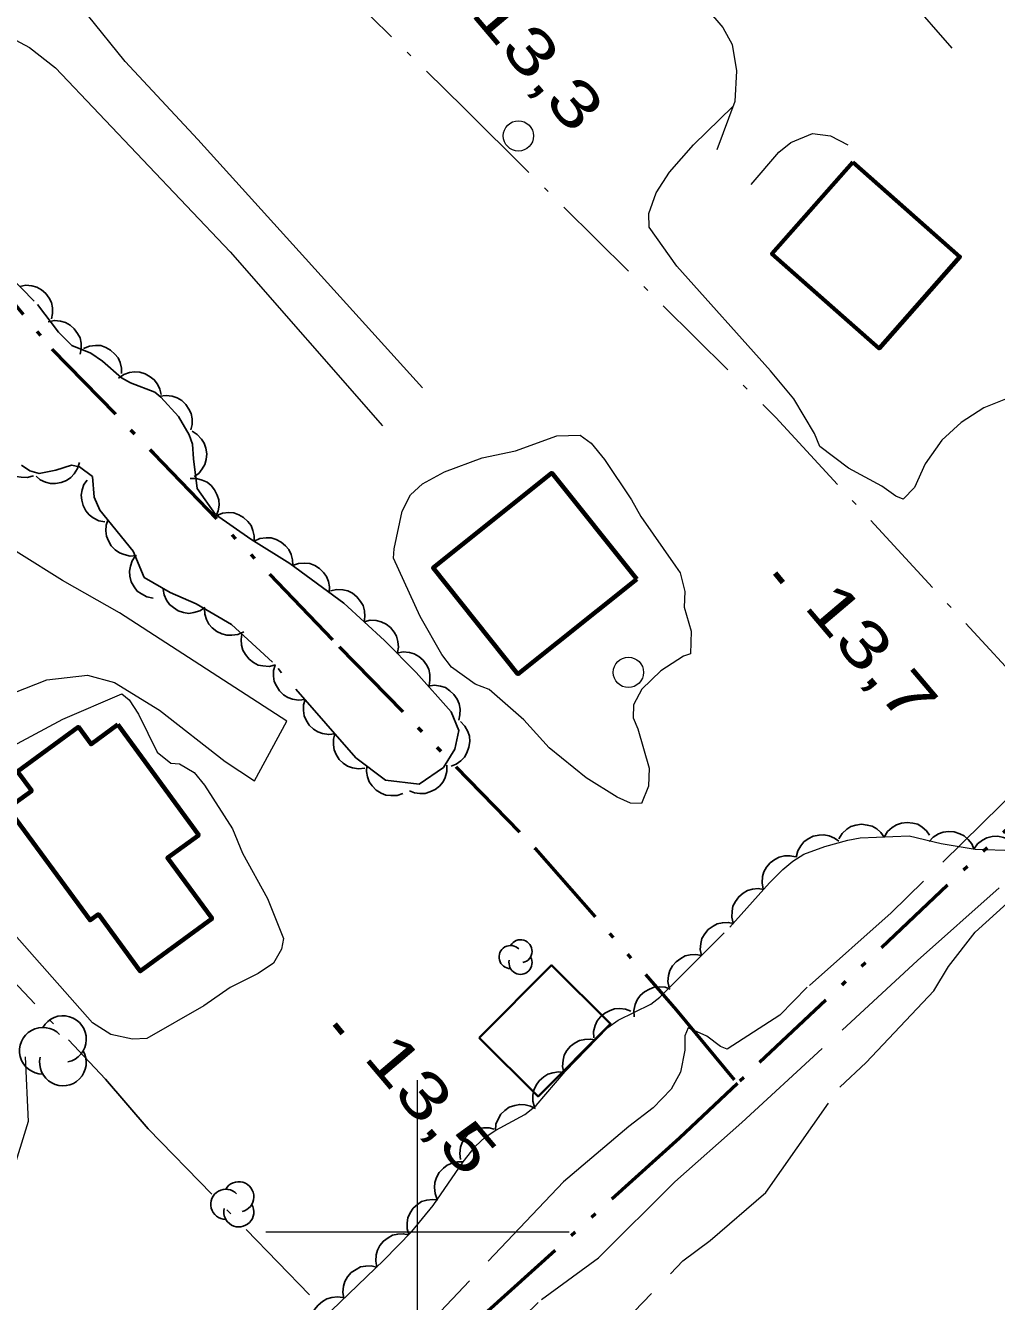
# Model space of a CAD drawing. Extents: x 386081 to 389416, y 5130568 to 5134082.
# Drawn here: x 387174.2 to 387238.2, y 5131995.4 to 5132079.6 of the extents above; entities that cross this region are included whole.
import ezdxf

# ---------------------------------------------------------------- set-up
doc = ezdxf.new("R2010")
doc.units = 0
doc.header["$LTSCALE"] = 1.2
for name, pattern in [('DASH_DOUBLE_DOT', [9.2, 5, -1.2, 0.3, -1.2, 0.3, -1.2]), ('DOT_DASHED', [7.7, 5, -1.2, 0.3, -1.2]), ('LONG_DASHED', [7.5, 6, -1.5])]:
    doc.linetypes.add(name, pattern=pattern)
for name, color, linetype, lineweight in [('19', 7, 'Continuous', 13), ('2', 7, 'Continuous', 13), ('3', 7, 'Continuous', 140), ('31', 7, 'Continuous', 70), ('36', 7, 'Continuous', 13), ('4', 7, 'DASH_DOUBLE_DOT', 53), ('41', 7, 'DOT_DASHED', 25), ('44', 7, 'Continuous', 25), ('61', 7, 'Continuous', 13)]:
    doc.layers.add(name, color=color, linetype=linetype, lineweight=lineweight)

msp = doc.modelspace()

# ---------------------------------------------------------------- linework, layer by layer
at = {"layer": '19'}
for points in [[(387235.25, 5132078.05), (387232.36, 5132081.38), (387229.88, 5132084.04), (387228.02, 5132082.24), (387226.25, 5132081.78), (387224.8, 5132082.21), (387223.27, 5132083.15), (387219.82, 5132086.04), (387214.56, 5132090.74), (387205.62, 5132099.47), (387202.19, 5132103.97), (387201.34, 5132105.59), (387201.05, 5132106.83), (387201.2, 5132108.09)], [(387195.48, 5132102.28), (387197.31, 5132101.55), (387199.4, 5132100.21), (387201.37, 5132098.51), (387212.87, 5132087.29), (387217.84, 5132082.11), (387220.13, 5132079.43), (387220.75, 5132078.3), (387221.02, 5132076.57), (387220.91, 5132074.55), (387219.74, 5132071.36)], [(387200.33, 5132055.65), (387185.51, 5132072.03), (387180.72, 5132077.18), (387178.24, 5132080.25), (387177.34, 5132081.59), (387176.74, 5132082.8), (387176.67, 5132083.63)], [(387171.93, 5132079.41), (387174.41, 5132078.09), (387176.13, 5132076.76), (387187.64, 5132064.63), (387197.68, 5132053.15)], [(387221.99, 5132069.07), (387223.82, 5132071.21), (387224.61, 5132071.84), (387226.04, 5132072.44), (387227.22, 5132072.28), (387228.37, 5132071.69)], [(387172.65, 5132035.26), (387175.55, 5132036.4), (387178.24, 5132036.72), (387180.02, 5132036.24), (387182.98, 5132034.41), (387187.32, 5132031.03), (387189.24, 5132029.75), (387191.38, 5132033.67), (387180.35, 5132040.82), (387176.6, 5132042.96), (387167.93, 5132048.36)], [(387174.13, 5132011.55), (387174.32, 5132007.28), (387173.26, 5132003.79)]]:
    msp.add_lwpolyline(points, dxfattribs=at)
at = {"layer": '2'}
for points in [[(387239.21, 5132055.08), (387237.34, 5132054.34), (387235.84, 5132053.38), (387234.57, 5132052.2), (387233.47, 5132050.65), (387232.76, 5132049.09), (387232.02, 5132048.32), (387231.52, 5132048.51), (387230.6, 5132049.18), (387228.42, 5132050.36), (387226.52, 5132051.79), (387226.16, 5132052.65), (387224.8, 5132054.94), (387223.27, 5132056.79), (387217.1, 5132063.68), (387215.26, 5132066.25), (387215.24, 5132067.15), (387215.73, 5132068.51), (387216.62, 5132069.88), (387218.2, 5132071.68), (387220.79, 5132074.21)], [(387171.81, 5132031.24), (387176.62, 5132033.82), (387180.51, 5132035.48), (387180.98, 5132035.09), (387181.61, 5132034.15), (387182.83, 5132031.63), (387183.74, 5132030.92), (387184.31, 5132030.86), (387185.28, 5132030.3), (387185.95, 5132029.46), (387187.79, 5132026.59), (387188.47, 5132024.98), (387190.11, 5132021.98), (387191.17, 5132019.34), (387191.04, 5132018.65), (387190.5, 5132017.73), (387189.5, 5132017.04), (387187.65, 5132016.11), (387185.91, 5132014.9), (387182.15, 5132012.76), (387181.2, 5132012.71), (387179.78, 5132013.03), (387178.56, 5132013.78), (387172.93, 5132020.19)]]:
    msp.add_lwpolyline(points, dxfattribs=at)
at = {"layer": '2', "linetype": 'LONG_DASHED'}
for points in [[(387264.61, 5132052.7), (387262.48, 5132051.58), (387256.69, 5132046.94), (387254.18, 5132044.13), (387249.06, 5132039), (387244.41, 5132034.13), (387239.76, 5132029.44), (387231.22, 5132021.04), (387225.69, 5132016.13), (387223.88, 5132014.3), (387220.42, 5132012.05), (387219.97, 5132012.22), (387219.08, 5132012.91), (387217.84, 5132013.45), (387217.63, 5132012.93), (387217.63, 5132011.99), (387217.33, 5132010.54), (387216.72, 5132009.42), (387215.53, 5132008.18), (387213.92, 5132006.96), (387209.62, 5132003.3), (387196.04, 5131989.01), (387193.68, 5131986.98), (387181.72, 5131978.95)], [(387195.16, 5131966.17), (387195.01, 5131966.62), (387195.11, 5131967.92), (387195.83, 5131972.22), (387197.11, 5131974.15), (387201.28, 5131979.8), (387206.75, 5131986.68), (387210.42, 5131990.76), (387217.49, 5131998.09), (387219.3, 5131999.44), (387222.96, 5132002.61), (387227.84, 5132009.55), (387229.57, 5132011.18), (387234.04, 5132015.9), (387235, 5132017.51), (387236.75, 5132019.76), (387262.28, 5132042.99)], [(387202.76, 5131990.36), (387208.17, 5131995.54), (387211.92, 5131998.3), (387216.97, 5132003.3), (387221.38, 5132007.21), (387232.96, 5132017.9), (387247.54, 5132030.88)]]:
    msp.add_lwpolyline(points, dxfattribs=at)
at = {"layer": '2'}
msp.add_lwpolyline([(387217, 5132043.9), (387217.31, 5132043.46), (387217.63, 5132042.24), (387217.58, 5132041.19), (387218.03, 5132039.61), (387217.99, 5132038.13), (387217.54, 5132037.96), (387216.04, 5132036.99), (387214.79, 5132035.79), (387214.24, 5132034.75), (387214.22, 5132033.91), (387214.52, 5132033.18), (387215.27, 5132030.58), (387215.23, 5132029.4), (387214.76, 5132028.25), (387214.04, 5132028.28), (387213.16, 5132028.66), (387211.12, 5132029.94), (387208.67, 5132031.92), (387207.01, 5132033.76), (387204.71, 5132035.76), (387203.8, 5132036.11), (387202.24, 5132037.24), (387201.61, 5132038.07), (387200.18, 5132040.59), (387198.41, 5132044.42), (387198.45, 5132045.05), (387198.98, 5132047.53), (387199.54, 5132048.61), (387200.32, 5132049.32), (387201.77, 5132050.13), (387204.25, 5132051.04), (387206.46, 5132051.51), (387209.19, 5132052.49), (387210.72, 5132052.53), (387211.45, 5132052.01), (387212.33, 5132050.94), (387214.1, 5132048.28), (387214.71, 5132047.18)], close=True, dxfattribs=at)
at = {"layer": '3'}
for p, q in [((387223.57, 5132043.44), (387224.08, 5132042.83)), ((387194.54, 5132013.7), (387195.05, 5132013.09))]:
    msp.add_line(p, q, dxfattribs=at)
at = {"layer": '31'}
for points in [[(387228.69, 5132070.54), (387235.76, 5132064.3), (387230.43, 5132058.26), (387223.36, 5132064.5)], [(387214.46, 5132043.05), (387206.62, 5132036.79), (387201.02, 5132043.78), (387208.85, 5132050.05)], [(387180.23, 5132033.45), (387185.58, 5132026.17), (387183.51, 5132024.66), (387186.45, 5132020.66), (387181.72, 5132017.19), (387178.96, 5132020.95), (387178.41, 5132020.55), (387172.99, 5132027.94), (387174.56, 5132029.09), (387173.63, 5132030.36), (387177.64, 5132033.3), (387178.48, 5132032.16)]]:
    msp.add_lwpolyline(points, close=True, dxfattribs=at)
at = {"layer": '31', "lineweight": 35}
msp.add_lwpolyline([(387204.07, 5132012.8), (387208.84, 5132017.59), (387212.72, 5132013.73), (387207.95, 5132008.94)], close=True, dxfattribs=at)
at = {"layer": '36'}
for centre in [(387206.648, 5132072.27), (387213.901, 5132036.897)]:
    msp.add_circle(centre, 1, dxfattribs=at)
at = {"layer": '4'}
for points in [[(387318.59, 5132105.79), (387271.28, 5132059.47), (387242.97, 5132030.44), (387221.09, 5132009.79)], [(387165.87, 5132070.73), (387170.18, 5132065.12), (387175.88, 5132058.2), (387182.6, 5132051.34), (387194.84, 5132038.59), (387207.76, 5132025.29), (387217.04, 5132014.65), (387221.09, 5132009.79), (387217.26, 5132006.18), (387178.99, 5131971.65)]]:
    msp.add_lwpolyline(points, dxfattribs=at)
at = {"layer": '41'}
for points in [[(387187.42, 5132089.5), (387203.08, 5132074.09), (387223.62, 5132053.7), (387241.48, 5132034.32)], [(387144.02, 5132047.08), (387157.99, 5132032.87), (387179.42, 5132010.08)], [(387179.42, 5132010.08), (387182.25, 5132006.79), (387193.01, 5131995.72)]]:
    msp.add_lwpolyline(points, dxfattribs=at)
at = {"layer": '44', "linetype": 'DOT_DASHED'}
msp.add_lwpolyline([(387170.52, 5132065.66), (387174.95, 5132061.15), (387176.32, 5132059.34), (387177.21, 5132058.44), (387178.45, 5132057.94), (387179.24, 5132057.42), (387180.48, 5132056.32), (387181.07, 5132056), (387182.69, 5132055.38), (387183.07, 5132055.04), (387184.23, 5132053.78), (387184.95, 5132052.55), (387185.17, 5132051.95), (387185.22, 5132050.97), (387185.46, 5132049.03), (387186.68, 5132047.3), (387189.01, 5132045.69), (387191.58, 5132044.08), (387195.13, 5132041.47), (387197.82, 5132039), (387199.9, 5132036.9), (387202.22, 5132034.3), (387202.71, 5132033.07), (387202.45, 5132031.84), (387201.71, 5132030.62), (387200.1, 5132029.53), (387197.89, 5132029.79), (387195.93, 5132031.27), (387190.43, 5132037.57), (387187.74, 5132040.05), (387185.41, 5132041.42), (387183.69, 5132042.16), (387181.98, 5132043.16), (387181.25, 5132044.88), (387179.06, 5132047.6), (387178.69, 5132048.46), (387178.58, 5132049.81), (387177.72, 5132050.44), (387177.19, 5132050.57), (387176.15, 5132050.24), (387175.06, 5132050.01), (387174.45, 5132050.19), (387173.88, 5132050.55)], dxfattribs=at)
at = {"layer": '44'}
for points in [[(387173.77, 5132062.35), (387174.18, 5132062.43), (387174.58, 5132062.38), (387174.9, 5132062.3), (387175.21, 5132062.12), (387175.49, 5132061.88), (387175.71, 5132061.57), (387175.86, 5132061.28), (387175.93, 5132060.94), (387175.94, 5132060.56), (387175.87, 5132060.21)], [(387175.65, 5132060.02), (387176.06, 5132060.1), (387176.46, 5132060.05), (387176.78, 5132059.97), (387177.09, 5132059.79), (387177.37, 5132059.55), (387177.59, 5132059.24), (387177.75, 5132058.95), (387177.82, 5132058.61), (387177.83, 5132058.24), (387177.76, 5132057.89)], [(387177.98, 5132058.25), (387178.37, 5132058.41), (387178.77, 5132058.45), (387179.11, 5132058.44), (387179.44, 5132058.32), (387179.76, 5132058.15), (387180.04, 5132057.89), (387180.26, 5132057.64), (387180.4, 5132057.32), (387180.49, 5132056.96), (387180.49, 5132056.6)], [(387180.29, 5132056.3), (387180.64, 5132056.54), (387181.02, 5132056.66), (387181.35, 5132056.72), (387181.7, 5132056.69), (387182.05, 5132056.58), (387182.38, 5132056.39), (387182.64, 5132056.19), (387182.85, 5132055.91), (387183.01, 5132055.58), (387183.09, 5132055.23)], [(387183.02, 5132055.1), (387183.43, 5132055.16), (387183.83, 5132055.1), (387184.15, 5132055.01), (387184.45, 5132054.82), (387184.72, 5132054.57), (387184.93, 5132054.25), (387185.08, 5132053.96), (387185.13, 5132053.61), (387185.13, 5132053.24), (387185.05, 5132052.89)], [(387185.13, 5132052.8), (387185.48, 5132052.59), (387185.76, 5132052.28), (387185.94, 5132052.01), (387186.05, 5132051.68), (387186.1, 5132051.31), (387186.06, 5132050.93), (387185.98, 5132050.61), (387185.8, 5132050.31), (387185.57, 5132050.02), (387185.28, 5132049.81)], [(387174.68, 5132049.85), (387174.27, 5132049.74), (387173.87, 5132049.76), (387173.54, 5132049.82), (387173.23, 5132049.97), (387172.93, 5132050.19), (387172.69, 5132050.49), (387172.51, 5132050.76), (387172.42, 5132051.1), (387172.38, 5132051.47), (387172.42, 5132051.83)], [(387177.71, 5132050.74), (387177.59, 5132050.33), (387177.37, 5132049.99), (387177.15, 5132049.75), (387176.85, 5132049.56), (387176.51, 5132049.42), (387176.13, 5132049.36), (387175.81, 5132049.35), (387175.47, 5132049.45), (387175.13, 5132049.6), (387174.85, 5132049.83)], [(387179.39, 5132046.83), (387178.98, 5132046.9), (387178.62, 5132047.09), (387178.35, 5132047.29), (387178.14, 5132047.56), (387177.96, 5132047.89), (387177.87, 5132048.26), (387177.83, 5132048.58), (387177.89, 5132048.93), (387178.01, 5132049.28), (387178.21, 5132049.58)], [(387185.01, 5132049.68), (387185.42, 5132049.68), (387185.81, 5132049.57), (387186.12, 5132049.44), (387186.39, 5132049.22), (387186.62, 5132048.93), (387186.79, 5132048.59), (387186.9, 5132048.28), (387186.91, 5132047.93), (387186.86, 5132047.56), (387186.73, 5132047.22)], [(387186.76, 5132047.25), (387187.15, 5132047.4), (387187.55, 5132047.43), (387187.88, 5132047.41), (387188.21, 5132047.29), (387188.53, 5132047.11), (387188.81, 5132046.84), (387189.02, 5132046.59), (387189.15, 5132046.26), (387189.23, 5132045.9), (387189.23, 5132045.54)], [(387181.47, 5132044.61), (387181.05, 5132044.57), (387180.66, 5132044.66), (387180.34, 5132044.77), (387180.06, 5132044.98), (387179.81, 5132045.25), (387179.62, 5132045.58), (387179.49, 5132045.88), (387179.46, 5132046.23), (387179.48, 5132046.6), (387179.59, 5132046.94)], [(387189.23, 5132045.55), (387189.61, 5132045.72), (387190.02, 5132045.77), (387190.35, 5132045.77), (387190.68, 5132045.66), (387191.01, 5132045.49), (387191.3, 5132045.24), (387191.52, 5132045), (387191.66, 5132044.68), (387191.76, 5132044.32), (387191.77, 5132043.96)], [(387182.56, 5132041.8), (387182.15, 5132041.88), (387181.79, 5132042.07), (387181.52, 5132042.26), (387181.31, 5132042.54), (387181.13, 5132042.86), (387181.04, 5132043.24), (387181, 5132043.56), (387181.07, 5132043.91), (387181.19, 5132044.26), (387181.39, 5132044.56)], [(387191.76, 5132043.94), (387192.16, 5132044.08), (387192.56, 5132044.1), (387192.89, 5132044.08), (387193.22, 5132043.95), (387193.54, 5132043.75), (387193.8, 5132043.48), (387194, 5132043.22), (387194.13, 5132042.89), (387194.2, 5132042.53), (387194.18, 5132042.17)], [(387185.99, 5132041.17), (387185.64, 5132040.95), (387185.24, 5132040.84), (387184.92, 5132040.79), (387184.57, 5132040.84), (387184.22, 5132040.96), (387183.9, 5132041.17), (387183.64, 5132041.37), (387183.45, 5132041.66), (387183.3, 5132042), (387183.23, 5132042.36)], [(387194.26, 5132042.27), (387194.67, 5132042.36), (387195.08, 5132042.34), (387195.4, 5132042.27), (387195.71, 5132042.11), (387196, 5132041.88), (387196.24, 5132041.58), (387196.41, 5132041.3), (387196.5, 5132040.96), (387196.53, 5132040.59), (387196.47, 5132040.24)], [(387188.54, 5132039.58), (387188.16, 5132039.4), (387187.76, 5132039.34), (387187.43, 5132039.34), (387187.09, 5132039.43), (387186.76, 5132039.59), (387186.46, 5132039.84), (387186.24, 5132040.07), (387186.08, 5132040.39), (387185.97, 5132040.74), (387185.95, 5132041.1)], [(387196.47, 5132040.24), (387196.88, 5132040.33), (387197.28, 5132040.31), (387197.61, 5132040.24), (387197.92, 5132040.08), (387198.21, 5132039.86), (387198.45, 5132039.55), (387198.62, 5132039.28), (387198.71, 5132038.93), (387198.74, 5132038.56), (387198.68, 5132038.21)], [(387190.63, 5132037.39), (387190.22, 5132037.29), (387189.81, 5132037.32), (387189.49, 5132037.38), (387189.18, 5132037.55), (387188.89, 5132037.77), (387188.65, 5132038.08), (387188.48, 5132038.36), (387188.4, 5132038.7), (387188.37, 5132039.07), (387188.42, 5132039.42)], [(387198.64, 5132038.17), (387199.05, 5132038.25), (387199.46, 5132038.2), (387199.78, 5132038.12), (387200.08, 5132037.94), (387200.36, 5132037.7), (387200.58, 5132037.39), (387200.74, 5132037.11), (387200.81, 5132036.76), (387200.82, 5132036.39), (387200.76, 5132036.04)], [(387192.58, 5132035.11), (387192.16, 5132035.06), (387191.76, 5132035.13), (387191.45, 5132035.23), (387191.16, 5132035.42), (387190.89, 5132035.68), (387190.69, 5132036.01), (387190.55, 5132036.3), (387190.5, 5132036.65), (387190.51, 5132037.02), (387190.61, 5132037.37)], [(387200.71, 5132035.99), (387201.12, 5132036.05), (387201.52, 5132035.98), (387201.84, 5132035.89), (387202.13, 5132035.69), (387202.4, 5132035.44), (387202.61, 5132035.12), (387202.75, 5132034.82), (387202.8, 5132034.47), (387202.79, 5132034.1), (387202.71, 5132033.75)], [(387194.55, 5132032.85), (387194.14, 5132032.8), (387193.74, 5132032.87), (387193.42, 5132032.97), (387193.13, 5132033.16), (387192.86, 5132033.42), (387192.66, 5132033.75), (387192.52, 5132034.04), (387192.48, 5132034.39), (387192.49, 5132034.76), (387192.58, 5132035.11)], [(387202.83, 5132033.65), (387203.12, 5132033.35), (387203.31, 5132032.99), (387203.42, 5132032.68), (387203.44, 5132032.33), (387203.39, 5132031.96), (387203.25, 5132031.6), (387203.1, 5132031.31), (387202.85, 5132031.07), (387202.55, 5132030.85), (387202.21, 5132030.72)], [(387196.52, 5132030.59), (387196.11, 5132030.54), (387195.71, 5132030.61), (387195.39, 5132030.71), (387195.1, 5132030.9), (387194.84, 5132031.16), (387194.64, 5132031.49), (387194.5, 5132031.78), (387194.45, 5132032.13), (387194.46, 5132032.5), (387194.55, 5132032.85)], [(387199.04, 5132028.92), (387198.65, 5132028.78), (387198.24, 5132028.77), (387197.91, 5132028.8), (387197.59, 5132028.93), (387197.28, 5132029.13), (387197.01, 5132029.41), (387196.82, 5132029.67), (387196.7, 5132030), (387196.63, 5132030.37), (387196.65, 5132030.73)], [(387201.94, 5132030.78), (387201.94, 5132030.36), (387201.82, 5132029.97), (387201.68, 5132029.67), (387201.45, 5132029.4), (387201.17, 5132029.17), (387200.82, 5132029.01), (387200.51, 5132028.91), (387200.16, 5132028.9), (387199.79, 5132028.96), (387199.46, 5132029.09)], [(387227.77, 5132025.92), (387227.99, 5132026.28), (387228.29, 5132026.55), (387228.57, 5132026.73), (387228.9, 5132026.83), (387229.27, 5132026.88), (387229.65, 5132026.83), (387229.97, 5132026.76), (387230.27, 5132026.57), (387230.55, 5132026.33), (387230.76, 5132026.04)], [(387230.76, 5132026.04), (387230.98, 5132026.4), (387231.29, 5132026.67), (387231.57, 5132026.85), (387231.9, 5132026.95), (387232.27, 5132027), (387232.65, 5132026.95), (387232.97, 5132026.88), (387233.27, 5132026.69), (387233.55, 5132026.45), (387233.76, 5132026.16)], [(387233.72, 5132025.74), (387234, 5132026.04), (387234.35, 5132026.25), (387234.66, 5132026.37), (387235.01, 5132026.41), (387235.38, 5132026.38), (387235.74, 5132026.26), (387236.04, 5132026.12), (387236.3, 5132025.88), (387236.53, 5132025.59), (387236.68, 5132025.26)], [(387224.96, 5132024.71), (387225.06, 5132025.12), (387225.27, 5132025.47), (387225.47, 5132025.73), (387225.76, 5132025.93), (387226.09, 5132026.09), (387226.47, 5132026.17), (387226.79, 5132026.19), (387227.14, 5132026.11), (387227.48, 5132025.97), (387227.77, 5132025.77)], [(387236.68, 5132025.25), (387236.92, 5132025.59), (387237.25, 5132025.83), (387237.54, 5132025.99), (387237.88, 5132026.07), (387238.25, 5132026.09), (387238.62, 5132026.01), (387238.94, 5132025.91), (387239.22, 5132025.71), (387239.48, 5132025.44), (387239.67, 5132025.14)], [(387222.79, 5132022.61), (387222.71, 5132023.02), (387222.75, 5132023.43), (387222.83, 5132023.75), (387223.01, 5132024.05), (387223.25, 5132024.33), (387223.56, 5132024.56), (387223.84, 5132024.72), (387224.19, 5132024.79), (387224.56, 5132024.8), (387224.91, 5132024.73)], [(387220.81, 5132020.35), (387220.71, 5132020.76), (387220.73, 5132021.16), (387220.79, 5132021.49), (387220.95, 5132021.8), (387221.17, 5132022.1), (387221.47, 5132022.34), (387221.75, 5132022.51), (387222.09, 5132022.6), (387222.46, 5132022.64), (387222.81, 5132022.59)], [(387218.71, 5132018.22), (387218.63, 5132018.63), (387218.67, 5132019.03), (387218.75, 5132019.35), (387218.93, 5132019.66), (387219.16, 5132019.94), (387219.48, 5132020.16), (387219.76, 5132020.32), (387220.1, 5132020.39), (387220.48, 5132020.41), (387220.83, 5132020.34)], [(387216.59, 5132016.1), (387216.51, 5132016.51), (387216.55, 5132016.91), (387216.63, 5132017.23), (387216.8, 5132017.54), (387217.04, 5132017.82), (387217.35, 5132018.04), (387217.64, 5132018.2), (387217.98, 5132018.27), (387218.35, 5132018.29), (387218.71, 5132018.22)], [(387214.28, 5132014.19), (387214.25, 5132014.6), (387214.35, 5132015), (387214.47, 5132015.31), (387214.68, 5132015.59), (387214.96, 5132015.83), (387215.3, 5132016.01), (387215.6, 5132016.13), (387215.95, 5132016.16), (387216.32, 5132016.13), (387216.66, 5132016.01)], [(387211.62, 5132012.8), (387211.6, 5132013.22), (387211.71, 5132013.61), (387211.84, 5132013.92), (387212.06, 5132014.19), (387212.34, 5132014.43), (387212.69, 5132014.6), (387212.99, 5132014.71), (387213.34, 5132014.73), (387213.71, 5132014.68), (387214.05, 5132014.56)], [(387209.64, 5132010.51), (387209.56, 5132010.92), (387209.6, 5132011.33), (387209.67, 5132011.65), (387209.85, 5132011.96), (387210.08, 5132012.24), (387210.39, 5132012.47), (387210.67, 5132012.63), (387211.02, 5132012.7), (387211.39, 5132012.72), (387211.74, 5132012.66)], [(387207.71, 5132008.22), (387207.6, 5132008.62), (387207.61, 5132009.03), (387207.66, 5132009.35), (387207.81, 5132009.67), (387208.02, 5132009.97), (387208.32, 5132010.22), (387208.59, 5132010.4), (387208.92, 5132010.5), (387209.29, 5132010.55), (387209.65, 5132010.51)], [(387205.13, 5132006.69), (387205.17, 5132007.11), (387205.33, 5132007.49), (387205.49, 5132007.77), (387205.75, 5132008.01), (387206.05, 5132008.22), (387206.42, 5132008.34), (387206.74, 5132008.41), (387207.09, 5132008.39), (387207.45, 5132008.29), (387207.77, 5132008.13)], [(387202.84, 5132004.77), (387202.78, 5132005.18), (387202.84, 5132005.58), (387202.93, 5132005.9), (387203.13, 5132006.2), (387203.38, 5132006.47), (387203.7, 5132006.67), (387203.99, 5132006.82), (387204.34, 5132006.87), (387204.71, 5132006.87), (387205.06, 5132006.78)], [(387201.3, 5132002.14), (387201.15, 5132002.53), (387201.12, 5132002.94), (387201.13, 5132003.27), (387201.25, 5132003.6), (387201.43, 5132003.92), (387201.7, 5132004.2), (387201.95, 5132004.41), (387202.28, 5132004.54), (387202.64, 5132004.62), (387203, 5132004.62)], [(387199.43, 5131999.8), (387199.31, 5132000.2), (387199.31, 5132000.61), (387199.36, 5132000.93), (387199.51, 5132001.25), (387199.72, 5132001.56), (387200, 5132001.81), (387200.27, 5132002), (387200.61, 5132002.1), (387200.98, 5132002.15), (387201.33, 5132002.12)], [(387197.32, 5131997.67), (387197.24, 5131998.08), (387197.27, 5131998.48), (387197.35, 5131998.8), (387197.52, 5131999.11), (387197.75, 5131999.4), (387198.06, 5131999.62), (387198.34, 5131999.79), (387198.69, 5131999.86), (387199.06, 5131999.88), (387199.41, 5131999.82)], [(387195.14, 5131995.61), (387195.07, 5131996.02), (387195.12, 5131996.42), (387195.2, 5131996.74), (387195.39, 5131997.04), (387195.63, 5131997.32), (387195.95, 5131997.53), (387196.24, 5131997.69), (387196.58, 5131997.75), (387196.95, 5131997.76), (387197.3, 5131997.68)], [(387193.08, 5131993.43), (387192.98, 5131993.83), (387193, 5131994.24), (387193.06, 5131994.56), (387193.21, 5131994.88), (387193.44, 5131995.17), (387193.73, 5131995.41), (387194.01, 5131995.59), (387194.35, 5131995.68), (387194.72, 5131995.72), (387195.08, 5131995.67)]]:
    msp.add_lwpolyline(points, dxfattribs=at)
at = {"layer": '44', "linetype": 'DOT_DASHED', "lineweight": 13}
msp.add_lwpolyline([(387194.32, 5131994.82), (387197.77, 5131998.13), (387199.62, 5132000.03), (387201.03, 5132001.75), (387203, 5132004.62), (387203.82, 5132005.66), (387204.46, 5132006.24), (387205.16, 5132006.71), (387207.07, 5132007.75), (387207.81, 5132008.33), (387209.72, 5132010.59), (387212.54, 5132013.47), (387213.22, 5132013.96), (387215.38, 5132015.03), (387215.98, 5132015.49), (387220.58, 5132020.09), (387223.21, 5132023.03), (387224.09, 5132023.91), (387224.75, 5132024.45), (387225.46, 5132024.9), (387226.85, 5132025.42), (387228.37, 5132025.84), (387229.17, 5132025.98), (387232.41, 5132026.11), (387234.52, 5132025.61), (387236.75, 5132025.25), (387239.38, 5132025.15)], dxfattribs=at)
at = {"layer": '44'}
for centre, radius, start, end in [((387206.133, 5132018.127), 0.762, 44.11537, 269.80396), ((387206.788, 5132018.508), 0.762, 282.26917, 149.72626), ((387206.788, 5132017.746), 0.762, 166.93686, 29.62122), ((387176.623, 5132012.715), 1.539, 282.26917, 149.72626), ((387175.299, 5132011.945), 1.539, 44.11537, 269.80396), ((387176.623, 5132011.175), 1.539, 166.93686, 29.62122), ((387187.36, 5132001.823), 0.994, 44.11537, 269.80396), ((387187.36, 5132001.823), 0.994, 44.11537, 269.80396), ((387188.215, 5132002.319), 0.994, 282.26917, 149.72626), ((387188.215, 5132002.319), 0.994, 282.26917, 149.72626), ((387188.215, 5132001.326), 0.994, 166.93686, 29.62122), ((387188.215, 5132001.326), 0.994, 166.93686, 29.62122)]:
    msp.add_arc(centre, radius, start, end, dxfattribs=at)
at = {"layer": '61'}
for p, q in [((387200, 5131990), (387200, 5132010)), ((387190, 5132000), (387210, 5132000))]:
    msp.add_line(p, q, dxfattribs=at)

# ---------------------------------------------------------------- texts
at = {"layer": '3', "width": 1.35}
for s, p in [('13,3   ', (387203.42, 5132080.32)), ('13,7   ', (387225.4, 5132041.22)), ('13,5   ', (387196.37, 5132011.48))]:
    msp.add_text(s, height=3, rotation=310.294, dxfattribs=at).set_placement(p)

doc.saveas('drawing.dxf')
